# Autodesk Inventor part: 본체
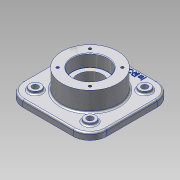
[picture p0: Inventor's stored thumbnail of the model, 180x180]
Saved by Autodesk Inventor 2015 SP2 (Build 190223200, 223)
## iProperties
Created: 2015-07
Part Number: 본체
Material: 일반
Document SubType Name: Modeling
Designer: AMC
Density: 1 g/cm^3
Appearance: 알루미늄 - 평지
Mass: 536.114 g
Surface Area: 802.271 cm^2
Volume: 536.114 cm^3
Author: AMC
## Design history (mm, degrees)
sketch "스케치1"
  geometry: L1 (-75, -75)-(75, -75); L2 (75, -75)-(75, 75); L3 (75, 75)-(-75, 75); L4 (-75, 75)-(-75, -75); L5 (-75, -75)-(75, 75); L6 (75, -75)-(-75, 75); 1 further point
  constraints: 12 end point, 2 midpoint, 2 parallel, 1 horizontal, 1 perpendicular
  dimensions: "d0" = 150 distance of L3.end L2.end; "d1" = 150 distance of L2.end L1.end
extrude "돌출1" new body sketch "스케치1" distance "d2" = 12; taper "d3" = 0 deg
sketch "스케치2"
  geometry: C1 r 50 at (0, 0); 1 further point
  constraints: 1 centre point, 1 coincident
  dimensions: "d4" = 100 diameter of C1
extrude "돌출2" join sketch "스케치2" distance "d5" = 35; taper "d7" = 0 deg; dims "d6" = 35, "d8" = 0
sketch "스케치3"
  geometry: L1 (-75, 75)-(-75, -75) reference; L2 (75, 75)-(-75, 75) reference; C1 r 10 at (-49, 49); C2 r 10 at (49, 49); C3 r 10 at (-49, -49); C4 r 10 at (49, -49); 1 further point
  constraints: 4 centre point
  dimensions: "d9" = 20 diameter of C1; "d10" = 20 diameter of C2; "d11" = 20 diameter of C3; "d12" = 20 diameter of C4; "d13" = 26 distance from line of L1 C1.centre; "d14" = 26 distance from line of C1.centre L2; "d15" = 98 distance of C3.centre C1.centre; "d16" = 98 distance of C2.centre C1.centre; "d17" = 98 distance of C4.centre C2.centre; "d18" = 98 distance of C4.centre C3.centre; "d19" = 26 distance from line of L2 C2.centre; "d20" = 26 distance from line of L1 C3.centre
extrude "돌출3" join sketch "스케치3" distance "d21" = 5; taper "d22" = 0 deg
hole "구멍1" diameter "d25" = 11; stored, may be unused: countersink angle "d29" = 90 deg, drill point angle "d31" = 118 deg; dims "d23" = 10, "d24" = 10, "d26" = 6, "d27" = 4, "d28" = 2, "d30" = 8
hole "구멍2" diameter "d34" = 11; stored, may be unused: countersink angle "d38" = 90 deg, drill point angle "d40" = 118 deg; dims "d32" = 10, "d33" = 10, "d35" = 6, "d36" = 4, "d37" = 2, "d39" = 8
hole "구멍3" diameter "d43" = 11; stored, may be unused: countersink angle "d47" = 90 deg, drill point angle "d49" = 118 deg; dims "d41" = 10, "d42" = 10, "d44" = 6, "d45" = 4, "d46" = 2, "d48" = 8
hole "구멍4" diameter "d52" = 11; stored, may be unused: countersink angle "d56" = 90 deg, drill point angle "d58" = 118 deg; dims "d50" = 10, "d51" = 10, "d53" = 6, "d54" = 4, "d55" = 2, "d57" = 8
hole "구멍5" diameter "d61" = 62; stored, may be unused: countersink angle "d65" = 90 deg, drill point angle "d67" = 0 deg; dims "d59" = 10, "d60" = 10, "d62" = 6, "d63" = 4, "d64" = 2, "d66" = 22
hole "구멍6" diameter "d70" = 45; stored, may be unused: countersink angle "d74" = 90 deg, drill point angle "d76" = 0 deg; dims "d71" = 6, "d72" = 62, "d73" = 22, "d75" = 22, "d114" = 10, "d115" = 10
sketch "스케치4"
  geometry: L1 (0, 0)-(41, 0); L2 (0, 0)-(28.991, 28.991); A1 r 41 centre (0, 0) between (41, 0) and (28.991, 28.991); 1 further point
  constraints: 4 end point, 2 point on circle, 1 centre point, 1 coincident, 1 horizontal
  dimensions: "d77" = 82 diameter of A1; "d78" = 45 deg angle of L1 L2
hole "구멍7" sketch "스케치4" at (28.991, 28.991) diameter "d79" = 4.917; stored, may be unused: countersink angle "d83" = 90 deg, drill point angle "d85" = 118 deg; dims "d80" = 10, "d81" = 64, "d82" = 22, "d84" = 13
sketch "스케치5"
  geometry: L1 (0, 0)-(41, 0); L2 (0, 0)-(28.991, 28.991); A1 r 41 centre (0, 0) between (41, 0) and (28.991, 28.991); 1 further point
  constraints: 4 end point, 2 point on circle, 1 centre point, 1 coincident, 1 horizontal
  dimensions: "d89" = 82 diameter of A1; "d90" = 45 deg angle of L1 L2
hole "구멍8" sketch "스케치5" at (28.991, 28.991) diameter "d91" = 4.917; stored, may be unused: countersink angle "d95" = 90 deg, drill point angle "d97" = 118 deg; dims "d92" = 10, "d93" = 64, "d94" = 22, "d96" = 13
fillet "모깎기1" dims "d101" = 30
fillet "모깎기2" dims "d102" = 3
fillet "모깎기3" dims "d103" = 0.3
chamfer "모따기1" distance "d104" = 1; stored, may be unused: second distance "d105" = 2, angle "d106" = 45 deg
chamfer "모따기2" distance "d107" = 1; stored, may be unused: second distance "d108" = 2, angle "d109" = 45 deg
sketch "스케치6"
  geometry: 2 further points
  constraints: 1 vertical alignment, 1 other
  dimensions: "d110" = 65 distance of point (0, 0) point (0, 65)
feature "엠보싱1" sketch "스케치6" dims "d0" = 150, "d1" = 150, "d9" = 20, "d10" = 20, "d11" = 20, "d12" = 20, "d13" = 26, "d14" = 26, "d15" = 98, "d16" = 98, "d17" = 98, "d18" = 98, "d19" = 26, "d20" = 26, "d111" = 1, "d112" = 0
fillet "모깎기4" dims "d113" = 3
node "솔리드1"
pattern_circular "원형 패턴1" dims angle "d87" = 360 deg
pattern_circular "원형 패턴2" dims angle "d99" = 360 deg
